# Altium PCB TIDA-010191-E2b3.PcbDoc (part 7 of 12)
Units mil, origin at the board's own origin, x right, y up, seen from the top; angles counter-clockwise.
Board outline 9842.52 x 9842.4 mil, 6 copper layers (Layer 1 - Top Layer, Layer 2 - GND Layer, Layer 3 - Signal, Layer 4 - Signal, Layer 5 - GND, Bottom Layer), stack 59.9 mil thick; 1178 components, 642 nets, 3329 pads, 2967 vias.
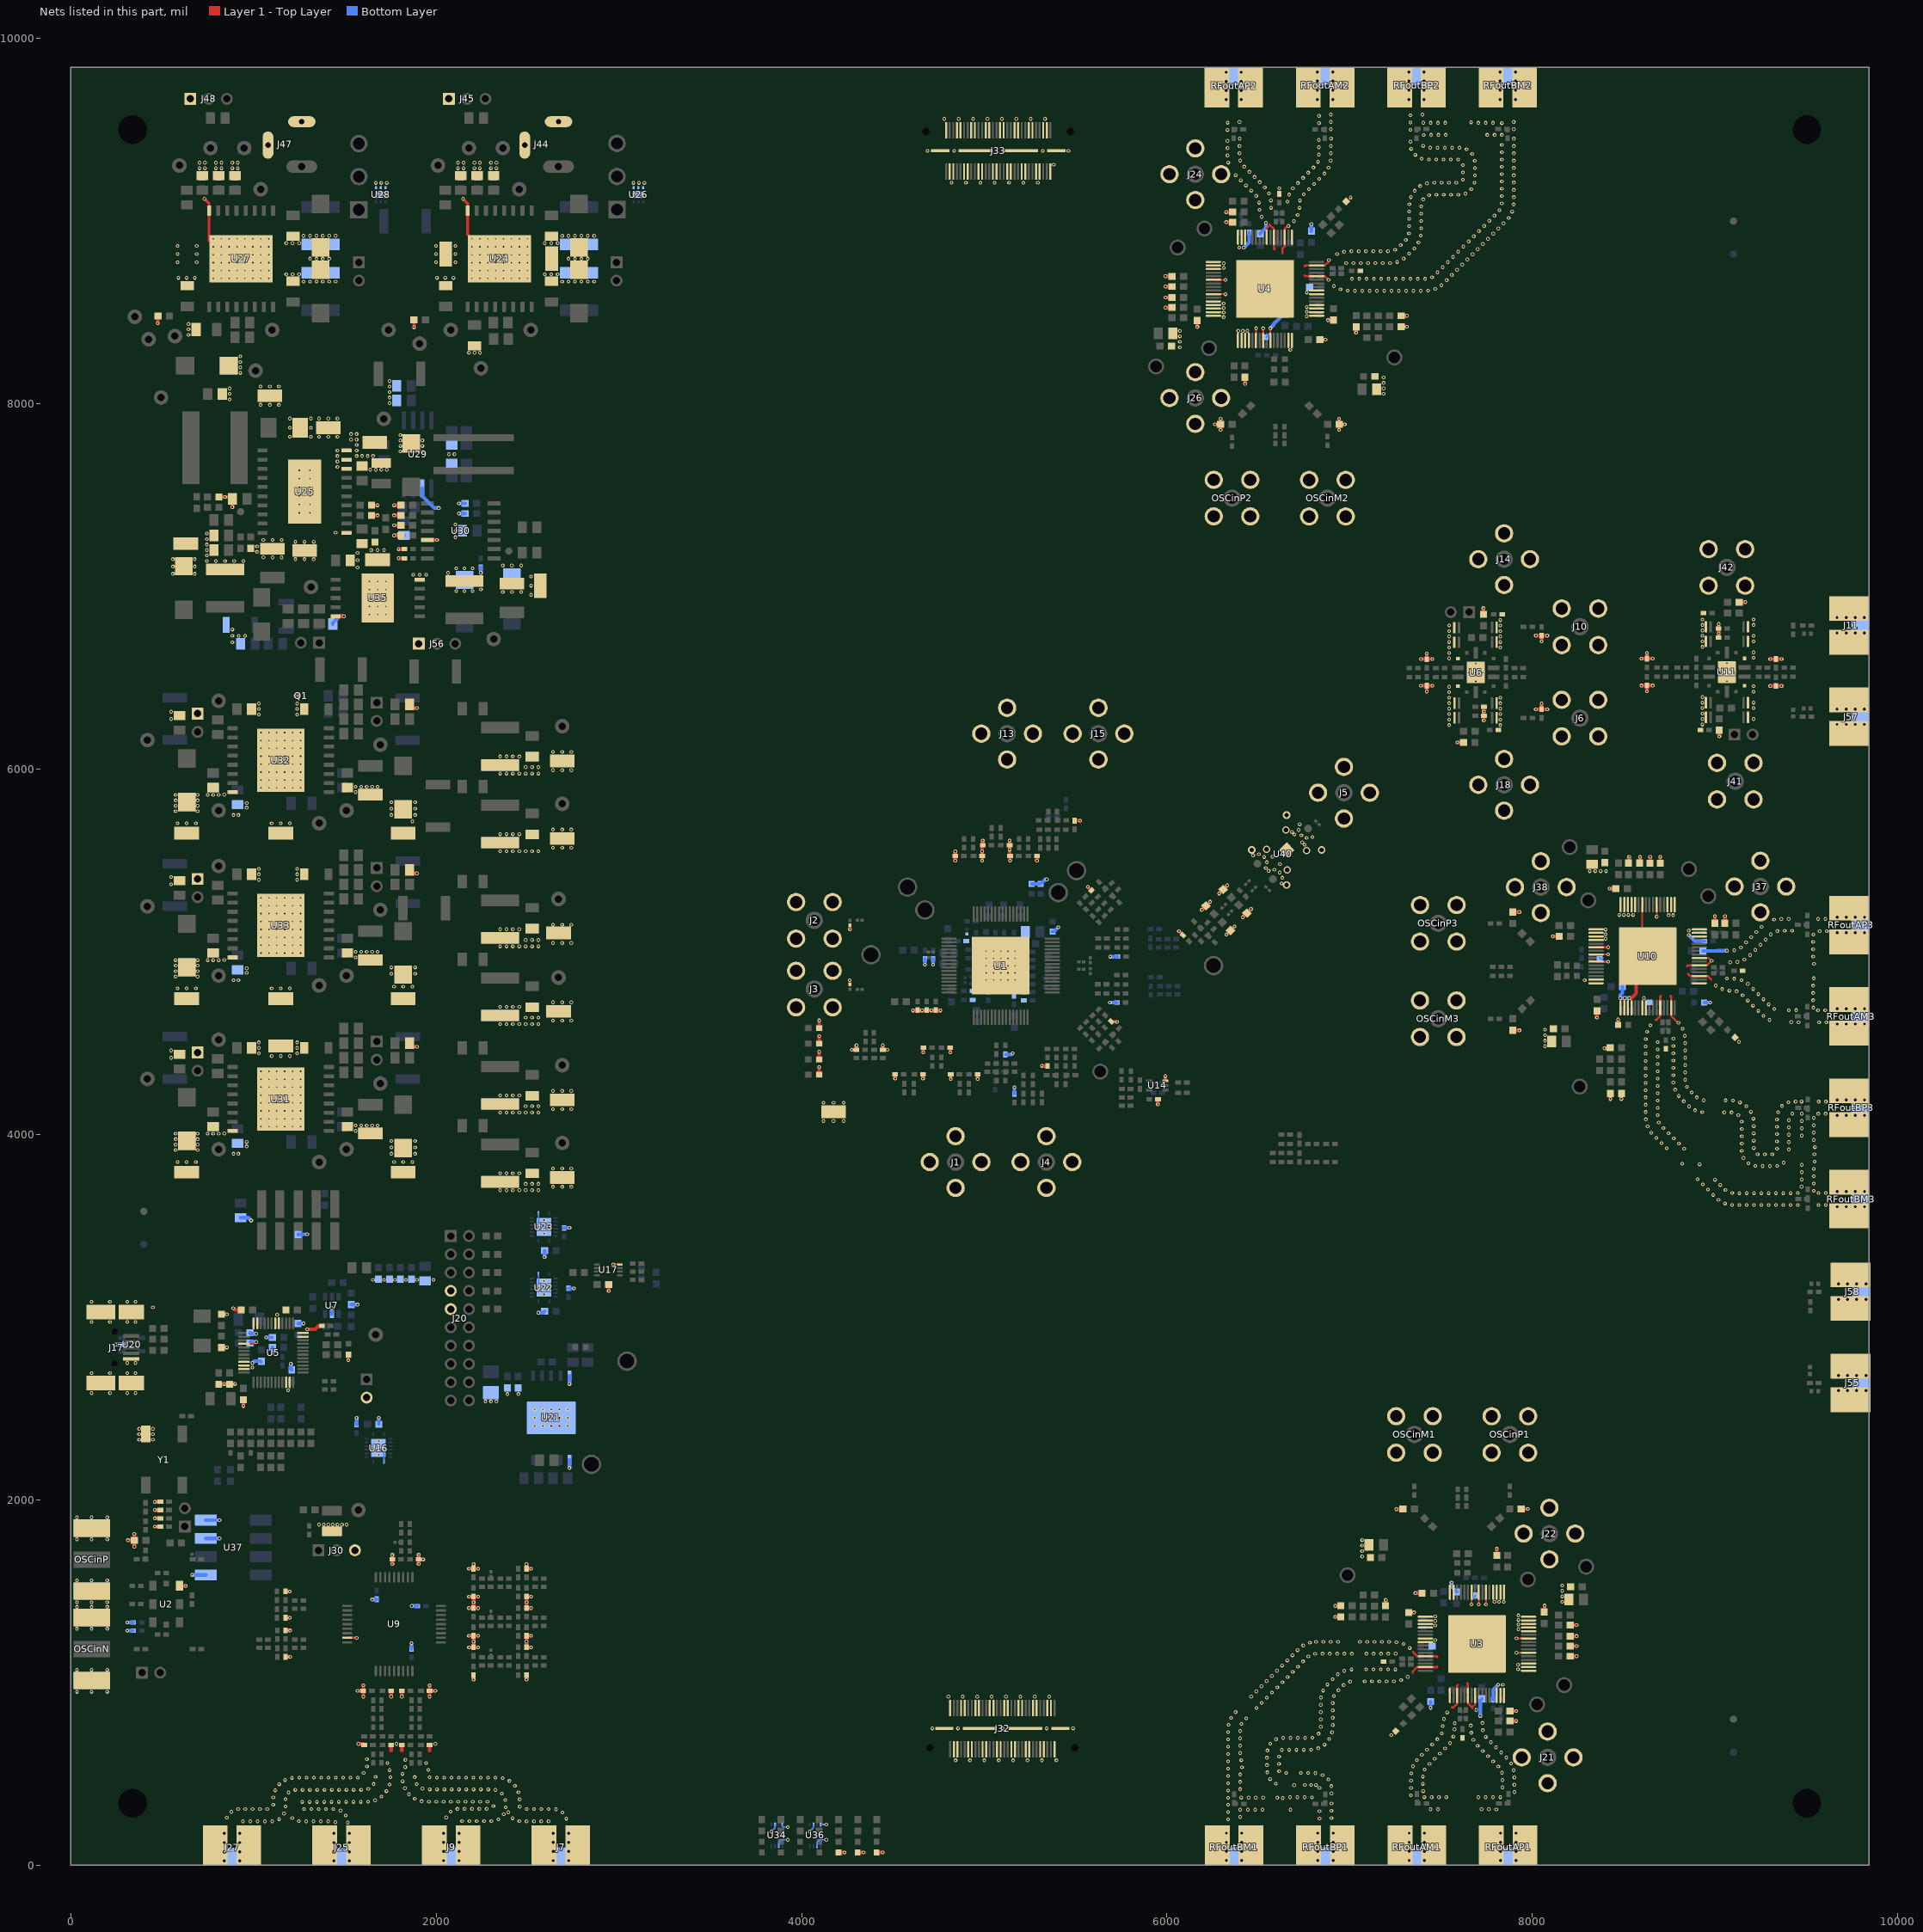
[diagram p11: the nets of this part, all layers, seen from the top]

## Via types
v1: diameter 20, hole 10, Layer 1 - Top Layer to Bottom Layer, tented both sides, 2595 vias
v2: diameter 19.68, hole 7.87, Layer 1 - Top Layer to Bottom Layer, 308 vias
v3: diameter 19.68, hole 7.87, Layer 1 - Top Layer to Bottom Layer, tented both sides, 25 vias
v4: diameter 20, hole 10, Layer 1 - Top Layer to Bottom Layer, 21 vias
v5: diameter 41, hole 25, Layer 1 - Top Layer to Bottom Layer, 10 vias
v6: diameter 24, hole 12, Layer 1 - Top Layer to Bottom Layer, tented both sides, 4 vias
v7: diameter 24, hole 8, Layer 1 - Top Layer to Bottom Layer, tented both sides, 1 vias
v8: diameter 24/24/24/24/24/24 (per signal layer), hole 8, Layer 1 - Top Layer to Bottom Layer, tented both sides, 1 vias
v9: diameter 30, hole 12, Layer 1 - Top Layer to Bottom Layer, tented both sides, 1 vias
v10: diameter 20/20/20/20/20/20 (per signal layer), hole 10, Layer 1 - Top Layer to Bottom Layer, tented both sides, 1 vias

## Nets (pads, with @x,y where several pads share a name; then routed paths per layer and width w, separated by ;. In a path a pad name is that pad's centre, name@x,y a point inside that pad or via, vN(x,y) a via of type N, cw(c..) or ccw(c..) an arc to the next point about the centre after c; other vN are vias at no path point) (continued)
GND: C1.2 C2.2 C7.2 C10.2 C11.2 C13.1 C14.2 C18.1 C19.1 C20.1 C21.1 C22.1 C23.2 C24.2 C25.2 C26.1 C27.2 C28.2 C29.2 C30.2 C31.1 C32.2 C33.2 C34.2 C35.2 C40.1 C41.2 C42.1 C43.2 C45.2 C46.1 C47.1 C49.1 C50.1 C51.1 C52.1 C53.1 C54.1 C55.1 C56.1 C58.1 C59.2 C61.2 C62.2 C63.2 C67.2 C68.2 C73.1 C74.2 C75.2 C76.1 C77.2 C78.2 C83.1 C84.1 C85.1 C93.2 C94.2 C95.2 C96.2 C97.2 C98.1 C99.2 C100.1 C101.2 C102.2 C103.2 C104.2 C106.2 C107.2 C108.2 C109.2 C110.2 C111.2 C112.2 C113.1 C114.2 C115.1 C117.2 C121.1 C122.1 C123.1 C124.1 C125.1 C126.2 C127.1 C128.1 C129.1 C130.1 C131.1 C138.1 C139.1 C140.1 C143.1 C144.2 C145.1 C147.2 C148.2 C149.2 C150.1 C151.2 C152.2 C154.1 C155.1 C156.1 C157.1 C159.2 C160.1 C161.1 C162.1 C163.1 C164.1 C165.1 C167.1 C168.2 C169.1 C170.1 C171.2 C173.1 C174.2 C175.2 C180.2 C182.2 C183.2 C184.2 C185.2 C186.1 C187.1 C188.1 C189.1 C190.2 C196.2 C197.2 C198.2 C199.2 C200.1 C201.2 C205.2 C206.2 C208.1 C209.2 C210.2 C211.1 C212.2 C213.2 C218.2 C219.2 C220.2 C221.2 C222.2 C226.1 C227.2 C228.1 C230.2 C231.2 C232.2 C233.2 C234.2 C235.2 C236.2 C237.2 C238.1 C239.2 C240.2 C241.2 C242.2 C243.2 C244.2 C245.2 C246.1 C247.1 C248.2 C252.2 C253.2 C254.1 C255.2 C256.1 C257.2 C258.2 C259.2 C260.2 C261.2 C262.1 C263.1 C265.2 C266.2 C267.1 C268.1 C269.2 C270.2 C272.2 C273.2 C274.2 C275.2 C276.2 C277.2 C278.2 C279.2 C280.1 C281.1 C282.2 C283.2 C284.2 C285.2 C286.1 C287.1 C288.2 C289.2 C291.2 C292.2 C293.2 C294.2 C295.2 C296.2 C297.2 C298.2 C299.1 C300.1 C301.2 C302.2 C303.2 C304.2 C305.1 C306.1 C307.2 C308.2 C310.2 C311.2 C312.2 C313.2 C314.2 C315.2 C326.2 C327.2 C328.2 C329.2 C334.2 C335.2 C337.2 C339.1 C340.1 C341.2 C342.2 C343.2 C344.2 C346.2 C348.2 C349.2 C350.2 C351.2 C352.2 C353.2 C354.2 C355.2 C356.2 D1.2 D2.2 D3.2 D4.2 D5.2 D6.2 D10.2 D12.2 D13.2 D18.2 D19.2 D20.2 D22.1 J1.2 J1.3 J1.4 J1.5 J2.2 J2.3 J2.4 J2.5 J3.2 J3.3 J3.4 J3.5 J4.2 J4.3 J4.4 J4.5 J5.2 J5.3 J5.4 J5.5 J6.2 J6.3 J6.4 J6.5 J7.2 J7.3 J7.4 J9.2 J9.3 J9.4 J10.2 J10.3 J10.4 J10.5 J11.2 J11.3 J11.4 J13.2 J13.3 J13.4 J13.5 J14.2 J14.3 J14.4 J14.5 J15.2 J15.3 J15.4 J15.5 J17.5 J17.6 J17.7 J17.8 J17.9 J18.2 J18.3 J18.4 J18.5 J20.7 J20.9 J21.2 J21.3 J21.4 J21.5 J22.2 J22.3 J22.4 J22.5 J24.2 J24.3 J24.4 J24.5 J25.2 J25.3 J25.4 J26.2 J26.3 J26.4 J26.5 J27.2 J27.3 J27.4 J30.3 J32.2 J32.3 J32.5 J32.8 J32.10 J32.11 J32.13 J32.16 J32.18 J32.19 J32.21 J32.24 J32.26 J32.27 J32.29 J32.32 J32.34 J32.35 J32.37 J32.40 J32.42 J32.43 J32.45 J32.48 J32.50 J32.51 J32.53 J32.56 J32.58 J32.59 J32.MP1 J32.MP2 J32.MP3 J32.MP4 J33.2 J33.3 J33.5 J33.8 J33.10 J33.11 J33.13 J33.16 J33.18 J33.19 J33.21 J33.24 J33.26 J33.27 J33.29 J33.32 J33.34 J33.35 J33.37 J33.40 J33.42 J33.43 J33.45 J33.48 J33.50 J33.51 J33.53 J33.56 J33.58 J33.59 J33.MP1 J33.MP2 J33.MP3 J33.MP4 J37.2 J37.3 J37.4 J37.5 J38.2 J38.3 J38.4 J38.5 J39.2 J41.2 J41.3 J41.4 J41.5 J42.2 J42.3 J42.4 J42.5 J44.2 J44.3 J45.1 J47.2 J47.3 J48.1 J50.1 J52.1 J54.1 J55.2 J55.3 J55.4 J56.1 J57.2 J57.3 J57.4 J58.2 J58.3 J58.4 NT2.2 OSCinM1.2 OSCinM1.3 OSCinM1.4 OSCinM1.5 OSCinM2.2 OSCinM2.3 OSCinM2.4 OSCinM2.5 OSCinM3.2 OSCinM3.3 OSCinM3.4 OSCinM3.5 OSCinN.2 OSCinN.3 OSCinN.4 OSCinN.5 OSCinP1.2 OSCinP1.3 OSCinP1.4 OSCinP1.5 OSCinP2.2 OSCinP2.3 OSCinP2.4 OSCinP2.5 OSCinP3.2 OSCinP3.3 OSCinP3.4 OSCinP3.5 OSCinP.2 OSCinP.3 OSCinP.4 OSCinP.5 Q1.3 R15.1 R16.1 R17.1 R18.1 R23.1 R24.1 R28.1 R34.2 R35.1 R40.2 R52.1 R53.2 R60.2 R61.2 R64.2 R65.2 R66.1 R67.1 R96.2 R99.1 R100.2 R104.2 R108.1 R110.1 R113.1 R118.2 R119.2 R123.1 R129.1 R133.1 R134.1 R139.1 R140.1 R153.2 R171.1 R174.1 R213.2 R214.2 R264.2 R267.2 R268.2 R270.2 R277.2 R285.1 R291.1 R297.1 R298.1 R299.2 R304.1 R318.1 R322.2 R329.1 R330.1 R334.2 R335.2 R337.1 R339.2 R342.2 R345.1 R348.2 R351.1 R366.2 R371.1 R375.1 R376.1 R379.1 R380.1 R389.1 R390.1 R401.1 R402.1 R403.1 R404.1 R412.2 R414.2 R415.1 R416.1 R417.1 R418.1 R419.1 R421.1 R426.1 R427.1 R434.1 R435.1 R436.1 R437.1 R444.1 R445.1 R446.1 R447.1 R454.1 R455.1 R456.1 R457.1 R464.1 R465.1 R466.1 R467.1 R474.1 R475.1 R476.1 R477.1 R479.1 R480.1 R490.1 R491.1 R492.1 R493.1 R494.1 R495.1 R496.1 R497.1 R498.1 R499.1 R500.1 R501.1 R510.1 R512.1 R513.1 R521.1 R523.1 R524.1 R534.1 R536.1 R537.1 R551.1 R552.1 RFoutAM1.2 RFoutAM1.3 RFoutAM1.4 RFoutAM2.2 RFoutAM2.3 RFoutAM2.4 RFoutAM3.2 RFoutAM3.3 RFoutAM3.4 RFoutAP1.2 RFoutAP1.3 RFoutAP1.4 RFoutAP2.2 RFoutAP2.3 RFoutAP2.4 RFoutAP3.2 RFoutAP3.3 RFoutAP3.4 RFoutBM1.2 RFoutBM1.3 RFoutBM1.4 RFoutBM2.2 RFoutBM2.3 RFoutBM2.4 RFoutBM3.2 RFoutBM3.3 RFoutBM3.4 RFoutBP1.2 RFoutBP1.3 RFoutBP1.4 RFoutBP2.2 RFoutBP2.3 RFoutBP2.4 RFoutBP3.2 RFoutBP3.3 RFoutBP3.4 TP5.1 TP22.1 TP23.1 TP24.1 TP25.1 TP26.1 TP36.1 TP43.1 TP48.1 TP49.1 TP50.1 TP51.1 TP56.1 TP61.1 TP62.1 TP63.1 TP64.1 TP69.1 TP74.1 TP75.1 TP76.1 TP77.1 TP80.1 TP81.1 TP82.1 U1.65 U2.3@596.03,1530.27 U3.1 U3.2 U3.3 U3.4 U3.6 U3.8 U3.10 U3.15 U3.16 U3.17 U3.18 U3.19 U3.20 U3.23 U3.24 U3.28 U3.31 U3.33 U3.35 U3.38 U3.40 U3.46 U3.47 U3.48 U3.49 U3.50 U3.51 U3.54 U3.58 U3.60 U3.61 U3.62 U3.63 U3.64 U3.65 U4.1 U4.2 U4.3 U4.4 U4.6 U4.8 U4.10 U4.15 U4.16 U4.17 U4.18 U4.19 U4.20 U4.23 U4.24 U4.28 U4.31 U4.33 U4.35 U4.38 U4.40 U4.46 U4.47 U4.48 U4.49 U4.50 U4.51 U4.54 U4.58 U4.60 U4.61 U4.62 U4.63 U4.64 U4.65 U5.4 U5.9 U5.10 U5.11 U5.22 U5.23 U5.35 U5.36 U5.41 U5.42 U5.47 U5.48 U6.11 U6.14 U6.15 U7.2 U9.8 U10.1 U10.2 U10.3 U10.4 U10.6 U10.8 U10.10 U10.15 U10.16 U10.17 U10.18 U10.19 U10.20 U10.23 U10.24 U10.28 U10.31 U10.33 U10.35 U10.38 U10.40 U10.46 U10.47 U10.48 U10.49 U10.50 U10.51 U10.54 U10.58 U10.60 U10.61 U10.62 U10.63 U10.64 U10.65 U11.11 U11.14 U11.15 U14.3 U16.8 U16.17 U17.4 U20.2 U21.5 U21.6 U21.11@2630,2450 U22.8 U22.17 U23.8 U23.17 U24.8 U24.17 U25.1 U25.8 U25.9 U25.10 U25.21 U26.1 U26.2 U26.3 U26.7@3107.56,9145 U27.8 U27.17 U28.1 U28.2 U28.3 U28.7@1697.56,9145 U29.2 U30.12 U31.8 U31.17 U32.8 U32.17 U33.8 U33.17 U34.2 U34.4 U34.6 U35.5 U35.10 U35.11@1680,6937.56 U36.2 U36.4 U36.6 U37.1 U37.3 U37.4 U40.4 Y1.2 | length 14671.6
  Layer 1 - Top Layer w8: U5.4@948.58,2854.8 1001.56,2854.8 1011.75,2865 v1(1015,2865) ; v3(5090,4925) v3(5129.37,4925) 5160,4925 U1.65@5189.53,4895.47
  Layer 1 - Top Layer w10: v1(2970,3289.53) U17.4@3005.92,3289.53 ; U4.58@6253.61,8600.5 v1(6320,8600.5) ; U4.54@6253.61,8679.24 v1(6320,8679.24) ; U4.6@6486.88,8347.55 v1(6486.88,8413.94) ; U4.8@6526.25,8347.55 v1(6526.25,8413.94) ; U4.40@6545.93,8912.51 6546.28,8912.86 6546.28,8961.28 6557.5,8972.5 ; U4.10@6565.62,8347.55 v1(6565.62,8413.94) ; v1(7666.73,1429.04) U3.10@7666.73,1495.43 ; 7674.85,870.48 7686.07,881.7 U3.40@7686.07,930.13 ; v1(7706.1,1429.04) U3.8@7706.1,1495.43 ; v1(7745.47,1429.04) U3.6@7745.47,1495.43 ; v1(7912.35,1163.74) U3.54@7978.74,1163.74 ; v1(7912.35,1242.48) U3.58@7978.74,1242.48 ; U10.10@8348.05,4946.93 v1(8414.44,4946.93) ; U10.8@8348.05,4986.3 v1(8414.44,4986.3) ; U10.6@8348.05,5025.67 v1(8414.44,5025.67) ; U10.58@8601,5258.94 8601,5005.98 U10.65@8630.53,4976.46 ; v1(8679.74,5192.55) U10.54@8679.74,5258.94 ; U10.40@8913.01,4966.61 8965.39,4966.61 v1(8980.64,4951.36)
  Layer 1 - Top Layer w12: U9.8@1513.58,1245.48 v1(1565.15,1245.48) ; 6561.19,8980.15 6585.3,8956.03 U4.38@6585.3,8912.51 6585.3,8850.35 6589.36,8846.29 ; 6633,8827 6633,8852 6644.36,8863.36 U4.35@6644.36,8912.51 6644.36,8958.32 v1@6664.02,8977.98 ; 6752.35,8702.98 6756.41,8698.93 U4.28@6818.57,8698.93 6864.38,8698.93 v1(6884.04,8679.27) ; 6752.35,8753.93 6756.41,8757.98 U4.31@6818.57,8757.98 6863.89,8757.98 6884.69,8778.78 6884.69,8785.27 v1(6886.22,8786.8) ; 7345,1055 7345,1062.03 7367.97,1085 U3.31@7413.78,1085 7475.94,1085 7480,1089.06 ; 7346.6,1168.18 7358.46,1156.33 7358.46,1155.91 7370.31,1144.06 U3.28@7413.78,1144.06 7475.94,1144.06 7480,1140 ; 7560,865 7568.33,865 7587.99,884.66 U3.35@7587.99,930.47 7587.99,982.99 7592.05,987.05 ; 7642.99,996.69 7647.05,992.64 U3.38@7647.05,930.47 7647.05,886.95 7671.16,862.84 ; 8675.34,4628.5 8679.76,4628.5 ; 8683.49,4634.55 8699.43,4650.49 8699.43,4756.14 8703.48,4760.2 ; 8754.43,4760.2 8758.48,4756.14 8758.48,4650.46 8782.6,4626.34 8782.74,4626.34 8797.13,4611.96 v1(8799.29,4611.96) ; 8846.79,4923.19 8850.84,4927.24 U10.38@8913.01,4927.24 8956.53,4927.24 v1(8980.64,4951.36) ; 8851,4880 8862.81,4868.19 U10.35@8913.01,4868.19 8958.82,4868.19 8978.48,4848.53
  Layer 1 - Top Layer w15: v1(732.5,9122.5) 757.56,9097.44 U27.8@757.56,9058.5 757.56,8892.56 ; v1(2147.5,9122.5) 2172.56,9097.44 U24.8@2172.56,9058.5 2172.56,8926.69 v2(2195.98,8903.27) ; R100.2@4263.74,4822.72 v1(4263.74,4845) ; v1(4265,5124.72) R99.1@4265,5147.01
  Layer 1 - Top Layer w20: v1(313.5,1780) R171.1@348.5,1780 ; v1(348.5,1745) R171.1@348.5,1780 ; v1(348.5,1815) R171.1@348.5,1780 ; v1(461.26,1855) C19.1@491.38,1855 ; v1(461.26,1900) C22.1@491.38,1900 ; v1(461.26,1945) C83.1@491.38,1945 ; v1(461.26,1990) C84.1@491.38,1990 ; v1(476.92,8441.05) 476.92,8480.42 R480.1@477.5,8481 ; U2.3@596.03,1530.27 v1(630,1530.27) ; C112.2@810,2633.5 811.5,2635 v1(840,2635) C114.2@870.45,2635 ; R415.1@811.5,7490 v1(845,7490) C239.2@885,7490 ; C125.1@824.55,3016.63 C125.1@825,3017.09 825.45,3017.54 v1(854.55,3017.54) ; C126.2@825,2834.09 825.91,2835 v1(855,2835) ; C114.2@870,2634.09 870.91,2635 v1(900,2635) ; v1(885,7435) C239.2@885,7480 ; v1(890,3050) 900,3040 C110.2@933.5,3040 ; v1(945,2515) C108.2@945,2548.5 ; C115.1@1173.5,3035 C115.1@1178.5,3040 ; R34.2@1175,1355.38 v1(1200,1355.38) ; R40.2@1175,1499.62 v1(1200,1499.62) ; R299.2@1176,1141.38 v1(1201,1141.38) ; R270.2@1176,1285.62 v1(1201,1285.62) ; v1(1227.75,6401.42) Q1.3@1242.75,6401.42 ; v1(1295,2935) 1337.63,2935 1356.13,2953.5 R174.1@1374.88,2953.5 ; U35.10@1450.08,6837.56 v1(1495,6837.56) ; v1(1520,2765) D10.2@1520,2796.06 ; v1(1570.09,955) R402.1@1601.38,955 ; v1(1575,665) 1601.38,665 R404.1@1606.38,660 ; v1(1601.38,923.72) R402.1@1601.38,955 ; v1(1601.38,986.28) R402.1@1601.38,955 ; R414.2@1646.5,7390 v1(1680,7390) ; R412.2@1646.5,7445 v1(1680,7445) ; 1753.62,628.72 R403.1@1753.62,660 ; v1(1753.62,923.72) R401.1@1753.62,955 ; v1(1760.38,1650) R444.1@1760.38,1675 v1(1760.38,1700) ; v1(1770,7280) R499.1@1808.5,7280 ; v1(1770,7335) R501.1@1808.5,7335 ; v1(1770,7390) R496.1@1808.5,7390 ; v1(1770,7445) R498.1@1808.5,7445 ; v1(1795,7155) R497.1@1826.38,7155 ; v1(1795,7205) R500.1@1826.38,7205 ; 1812.38,628.72 R437.1@1812.38,660 ; v1(1812.38,923.72) R435.1@1812.38,955 ; R513.1@1855,4500 1855,4495.47 1870,4480.47 v1(1895,4480.47) ; R537.1@1855,5450 1855,5445.47 1870,5430.47 v1(1895,5430.47) ; R524.1@1855,6354.53 1855,6350 1870,6335 v1(1895,6335) ; R419.1@1878.5,8460 1879.5,8459 v1(1879.5,8419.24) ; v1(1904.62,1650) R445.1@1904.62,1675 ; v1(1904.62,1700) R445.1@1904.62,1675 ; v1(1929.62,1675) R445.1@1904.62,1675 ; U30.12@1951.93,7255 v1(2005,7255) ; 1964.62,628.72 R436.1@1964.62,660 ; v1(1964.62,923.72) R434.1@1964.62,955 ; v1(1964.62,986.28) R434.1@1964.62,955 ; v1(1995.91,955) R434.1@1964.62,955 ; v1(2180,1193.62) R475.1@2205,1193.62 ; v1(2180,1256.38) R465.1@2205,1256.38 ; v1(2180,1408.62) R464.1@2205,1408.62 ; v1(2180,1471.38) R455.1@2205,1471.38 ; v1(2180,1623.62) R454.1@2205,1623.62 ; v1(2205,1016.38) R474.1@2205,1041.38 ; v1(2205,1648.62) R454.1@2205,1623.62 ; v1(2230,1193.62) R475.1@2205,1193.62 ; v1(2230,1256.38) R465.1@2205,1256.38 ; v1(2230,1408.62) R464.1@2205,1408.62 ; v1(2230,1471.38) R455.1@2205,1471.38 ; v1(2230,1623.62) R454.1@2205,1623.62 ; v1(2495,1016.38) R476.1@2495,1041.38 ; v1(2495,1648.62) R456.1@2495,1623.62 v1(2520,1623.62) ; v1(2520,1193.62) R477.1@2495,1193.62 v1(2495,1225) R467.1@2495,1256.38 v1(2520,1256.38) ; v1(2520,1408.62) R466.1@2495,1408.62 v1(2495,1440) R457.1@2495,1471.38 v1(2520,1471.38) ; v1(2944.79,3144.63) C199.2@2944.79,3179.63 ; D2.2@4096.42,4328.46 v1(4096.42,4370) ; D1.2@4096.42,4412 v1(4096.42,4453.53) ; D4.2@4096.42,4498.46 v1(4096.42,4540) ; D3.2@4096.42,4583.46 v1(4096.42,4625) ; D18.2@4201.28,70.59 v1(4235,70.59) ; v1(4275.38,4463.76) R446.1@4300.38,4463.76 v1(4300.38,4488.76) ; D19.2@4306.28,70.59 v1(4340,70.59) ; D20.2@4411.28,70.59 v1(4445,70.59) ; v1(4444.62,4488.76) R447.1@4444.62,4463.76 v10(4469.62,4463.76) ; v1(4512.1,4306.16) R24.1@4512.1,4331.16 ; v1(4610,4680) v1(4660,4680) v1(4710,4680) v1(4760,4680) ; v1(4664.35,4306.16) R23.1@4664.35,4331.16 ; v1(4666.38,4450) R18.1@4666.38,4475 ; v1(4813.62,4450) R17.1@4813.62,4475 ; v1(4816.38,4305) R16.1@4816.38,4330 ; v1(4841.38,5500) R60.2@4841.38,5525 v1(4841.38,5550) ; v1(4963.62,4305) R15.1@4963.62,4330 ; v1(4988.62,5500) R61.2@4988.62,5525 v1(4988.62,5550) 4988.62,5583.19 4990.43,5585 R66.1@4991.38,5585 v1(4991.38,5610) ; v1(5138.62,5610) R67.1@5138.62,5585 v1(5138.62,5560) 5138.62,5526.81 5140.43,5525 R64.2@5141.38,5525 v1(5141.38,5500) ; v1(5288.62,5500) R65.2@5288.62,5525 ; v1(5315,4376.38) R339.2@5345,4376.38 ; R366.2@5495,5718.62 v1(5525,5718.62) ; v1(5566.7,5356.7) R291.1@5586.7,5336.7 ; R285.1@5694.7,4620.3 5697.45,4617.55 v1(5726.44,4617.55) ; v1(5950,4165) 5950,4193.58 C2.2@5950.51,4194.09 ; U14.3@5991.18,4300 v1(5991.18,4320) ; v1(5992.12,8527.44) C128.1@6027.12,8527.44 ; v1(5992.12,8582.44) C144.2@6027.12,8582.44 ; v1(5992.12,8642.44) C150.1@6027.12,8642.44 ; v1(5992.12,8698.82) C190.2@6027.12,8698.82 ; v1(6065.29,5114.2) 6087.56,5091.93 C40.1@6087.56,5091.7 C40.1@6087.56,5091.47 ; v1(6165.61,8420.94) C145.1@6165.61,8455.94 ; v1(6190,5230) 6212.27,5252.27 R119.2@6212.73,5252.27 v1(6235,5274.54) ; v1(6262.46,7888.07) R348.2@6293.41,7888.07 ; v1(6285.23,5320) R118.2@6307.5,5342.27 ; v1(6293.41,7857.12) R348.2@6293.41,7888.07 ; v1(6293.41,7919.01) R348.2@6293.41,7888.07 ; R118.2@6307.96,5342.27 v1(6330.23,5364.54) ; v1(6323.5,8995) C147.2@6358.5,8995 ; v1(6323.5,9050) C139.1@6358.5,9050 ; v1(6324.77,5095.46) 6347.04,5117.73 R110.1@6347.27,5117.73 6347.5,5117.73 v1(6369.77,5140) ; v1(6414.77,5190.46) 6437.04,5212.73 R108.1@6437.27,5212.73 6437.5,5212.73 v1(6459.77,5235) ; v1(6427.07,8110.21) C151.2@6427.07,8145.21 ; C143.1@6836.4,8352.44 v1(6867.35,8352.44) ; v1(6880,8458.5) C130.1@6910,8458.5 ; v1(6920,1360.54) R96.2@6950.95,1360.54 ; v1(6920,1420.54) C59.2@6950.95,1420.54 ; v1(6941.86,7857.12) R351.1@6941.86,7888.07 ; v1(6941.86,7919.01) R351.1@6941.86,7888.07 ; v1(6972.81,7888.07) R351.1@6941.86,7888.07 ; v1(7034.91,8390) C148.2@7034.91,8420.94 ; C62.2@7197.45,1422.04 v1(7197.45,1452.98) ; v1(7255,1950) 7289.25,1950 R113.1@7290.86,1951.61 ; C149.2@7281.4,8422.44 v1(7312.35,8422.44) ; R322.2@7281.4,8482.44 v1(7312.35,8482.44) ; C55.1@7322.35,1384.48 v1(7352.35,1384.48) ; v1(7359.67,1490.83) C98.1@7394.67,1490.83 ; v1(7390.09,6457.17) C67.2@7421.38,6457.17 ; v1(7390.09,6602.83) C68.2@7421.38,6602.83 ; v1(7421.38,6425.88) C67.2@7421.38,6457.17 ; v1(7421.38,6634.12) C68.2@7421.38,6602.83 ; v1(7452.66,6457.17) C67.2@7421.38,6457.17 ; v1(7452.66,6602.83) C68.2@7421.38,6602.83 ; v1(7588.94,6146.75) R140.1@7622.44,6146.75 ; C78.2@7731.49,6848.15 v1(7731.49,6881.75) ; v1(7733.94,6266.75) v1(7733.94,6316.75) 7733.94,6340.47 C77.2@7735.12,6341.65 ; C102.2@7805.28,1697.77 v1(7805.28,1732.77) ; C47.1@7876.5,790 v1(7911.5,790) ; C101.2@7876.5,845 v1(7911.5,845) ; R318.1@7893.15,4570.77 v1(7928.15,4570.77) ; R277.2@7893.15,5218.76 v1(7928.15,5218.76) ; R104.2@7940.13,1951.33 v1(7975.13,1951.33) ; v1(8018.72,6328.62) R123.1@8050,6328.62 ; v1(8018.72,6731.38) R129.1@8050,6731.38 ; v1(8050,6359.91) R123.1@8050,6328.62 ; v1(8050,6700.09) R129.1@8050,6731.38 ; C100.1@8066.74,1387.04 v1(8066.74,1422.04) ; v1(8081.28,6328.62) R123.1@8050,6328.62 ; v1(8081.28,6731.38) R129.1@8050,6731.38 ; v1(8110.71,5085.48) C180.2@8145.71,5085.48 ; C104.2@8206.5,1145 v1(8241.5,1145) ; C58.1@8206.5,1200 v1(8241.5,1200) ; C99.2@8206.5,1255 v1(8241.5,1255) ; C46.1@8206.5,1315 v1(8241.5,1315) ; v1(8352.65,4640.85) C167.1@8352.65,4675.85 ; v1(8394.16,4472.55) C175.2@8425.1,4472.55 ; v1(8421.44,5346.94) C169.1@8456.44,5346.94 ; v1(8426.6,4195.11) C171.2@8426.6,4226.06 ; C157.1@8468.44,4600 v1(8468.44,4630) ; v1(8486.6,4195.11) R264.2@8486.6,4226.06 ; C165.1@8529.32,5485.43 v1(8529.32,5520.43) ; v1(8530.5,4747.55) 8541.95,4747.55 8567.7,4773.3 8567.7,4913.63 U10.65@8630.53,4976.46 ; C168.2@8589.32,5485.43 v1(8589.32,5520.43) ; v1(8595.74,6458.13) R330.1@8627.02,6458.13 ; v1(8595.74,6605.37) R329.1@8627.02,6605.37 ; v1(8627.02,6426.84) R330.1@8627.02,6458.13 ; v1(8627.02,6636.65) R329.1@8627.02,6605.37 ; C170.1@8644.32,5485.43 v1(8644.32,5520.43) ; v1(8658.3,6458.13) R330.1@8627.02,6458.13 ; v1(8658.3,6605.37) R329.1@8627.02,6605.37 ; C183.2@8699.32,5485.43 v1(8699.32,5520.43) ; C174.2@8998.48,5161.69 v1(8998.48,5196.69) ; C212.2@9018.82,6720.09 9020,6721.28 v1(9020,6745) v1(9020,6795) ; v1(9022.44,6180) C213.2@9022.44,6213.6 ; C164.1@9053.48,5161.69 v1(9053.48,5196.69) ; R379.1@9131.5,6915 v1(9165,6915) ; v1(9301.16,6456.47) C206.2@9332.44,6456.47 v1(9363.72,6456.47) ; v1(9301.16,6603.72) C205.2@9332.44,6603.72 v1(9363.72,6603.72) ; R475.1@2205,1193.62 v1(2205,1225) R465.1@2205,1256.38 ; R464.1@2205,1408.62 v1(2205,1440) R455.1@2205,1471.38
  Bottom Layer w8: U16.17@1685,2285 1714.53,2255.47 U16.8@1714.53,2210.2 ; U22.8@2560.47,3237.36 2560.47,3192.09 U22.17@2590,3162.56 ; U23.8@2560.47,3569.8 2560.47,3524.53 U23.17@2590,3495 ; v1(3835,185) 3855.16,205.16 U34.2@3855.16,224.06 ; U34.6@3874.84,105.94 3874.84,126.63 3888.21,140 v1(3925,140) ; U34.4@3894.53,224.06 3894.53,215.47 3900,210 v1(3925,210) ; v1(4045,185) 4065.16,205.16 U36.2@4065.16,224.06 ; U36.6@4084.84,105.94 4084.84,126.63 4098.21,140 v1(4135,140) ; U36.4@4104.53,224.06 v1(4135,224.06)
  Bottom Layer w10: R342.2@6544.91,8364.69 6544.91,8368.62 6565.22,8388.94 6565.22,8413.54 v1(6565.62,8413.94) ; v1(7666.73,1429.04) 7667.13,1429.44 7667.13,1454.04 7687.45,1474.36 R214.2@7687.45,1478.3 ; R267.2@8365.18,4967.64 8369.12,4967.64 8389.44,4947.33 8414.04,4947.33 v1(8414.44,4946.93)
  Bottom Layer w20: v1(245,2851) U20.2@280.87,2851 ; v1(310,1285) C187.1@341.38,1285 ; v1(310,1330) C188.1@341.38,1330 ; v1(665,1590) U37.1@740,1590 ; U37.3@740,1790 v1(815,1790) ; U37.4@740,1890 v1(815,1890) ; NT2.2@930,3545 972.5,3545 v7(987.5,3530) ; C111.2@981.5,2860 986.5,2865 v1(1015,2865) ; C107.2@981.5,2915 986.5,2910 v1(1015,2910) ; v1(995,2750) 1005,2760 1036.69,2760 1041.5,2755.2 R153.2@1041.5,2758.5 ; v1(1070,2890) C117.2@1103.5,2890 ; C106.2@1103.5,2835 1105,2833.5 v1(1105,2805) ; v1(1205,2745) 1205,2717.09 C109.2@1210,2712.09 ; C113.1@1245,2966.5 v1(1275,2966.5) ; R304.1@1245,3454.06 1245.94,3455 v1(1295,3455) ; U7.2@1430,3018.35 v1(1430,3050) ; R552.1@1435,6795 1435,6801.5 1471.06,6837.56 v1(1495,6837.56) ; C124.1@1535,3069.59 v1(1570,3069.59) ; R371.1@1565,2413.62 v1(1565,2450) ; v1(1650,1455) 1673.62,1455 C95.2@1675,1456.38 ; C196.2@1686.5,2415 v1(1686.5,2450) ; v1(1770,7280) C261.2@1825,7280 ; C97.2@1865.15,1184.59 v1(1865.15,1215.96) ; v1(1866.38,1420) C96.2@1897.76,1420 ; U29.2@1924.09,7538.54 1924.09,7495.91 1990,7430 v1(2015,7430) ; v1(2125,7400) R495.1@2158.5,7400 ; v1(2125,7455) R493.1@2158.5,7455 ; v1(2245,7075) R494.1@2245,7106.38 ; v1(2560,3025) 2585.94,3025 C221.2@2593.5,3032.56 ; v1(2593.5,3330) C222.2@2593.5,3365 ; R390.1@2700,3488.62 2701.38,3490 v1(2730,3490) ; R389.1@2725,3158.62 v1(2755,3158.62) ; v1(2730,2175.16) U21.6@2730,2220.08 ; v1(2730,2635) U21.5@2730,2679.92 ; v1(4675,4930) C356.2@4675,4961.38 ; v1(4720,4930) C11.2@4720,4961.38 ; R345.1@5118.94,4438.62 5148.62,4438.62 v1(5155,4445) ; R337.1@5165,4223.62 v1(5165,4260) ; C20.1@5259.68,5372.56 C18.1@5307.5,5372.56 5308.48,5372.56 5333.43,5397.5 v1(5342.23,5397.5) ; C21.1@5373.57,5111.77 5381.77,5111.77 v1(5405,5135) ; v1(5688,4723.09) R297.1@5726.27,4723.09 ; v1(5690,4974.09) R298.1@5728.27,4974.09 ; v1(6420,8855) 6450,8885 R334.2@6450,8938.62 ; C152.2@6510,8931.5 6510,8932.48 6541.09,8963.58 v1(6541.09,8991.08) ; v1(6565.62,8413.94) 6582.22,8430.54 6582.22,8435.4 6616.51,8469.69 6628.63,8481.81 6636.3,8481.81 6645,8490.51 C129.1@6645,8491.5 ; C140.1@6790,8946.5 v1(6790,8985) ; v1(7442.35,862.98) C50.1@7442.35,896.49 ; v1(7557.35,1547.98) 7557.35,1525.13 7585,1497.48 C56.1@7585,1496.5 ; v1@7714.7,818.18 v1(7714.85,818.33) 7715,818.48 7715,904.14 C103.2@7722.35,911.49 ; R213.2@7784.74,907.42 7784.74,960.37 v1(7812.35,987.98) ; C155.1@8492.5,4810 8492.5,4775.35 8480.5,4763.35 v1(8480.5,4747.55) v1(8530.5,4747.55) ; v1(8855.5,5092.55) 8888.11,5059.94 R268.2@8941.06,5059.94 ; C182.2@8932.5,5005 9013.71,5005 9012.21,5006.5 v1(9063.79,5006.5) ; C154.1@8939.12,4722.55 v1(8972.62,4722.55)
  other v1: 1516.62,234.36 1448.36,236.32 943.02,241.35 983.02,241.35 1023.02,241.35 1063.02,241.35 1103.02,241.32 1288.68,241.35 1328.68,241.35 1368.68,241.35 1408.68,241.35 2495.52,241.35 2535.52,241.35 2575.52,241.35 2615.52,241.35 1248.7,242.54 2142.5,242.35 2182.5,242.35 2222.5,242.35 2262.5,242.35 2302.5,242.35 2455.53,242.3 6334.54,251.49 2341.39,251.7 1141.13,253.48 2713.21,255.77 6834.54,256.56 2418.8,258.14 1212.35,259.25 6899.79,259.01 854.91,260.9 2055.06,262.25 6399.79,264.96 1505.4,272.76 2370.07,279.59 1167.71,283.37 2691.47,289.35 2395.32,290.52 6334.54,291.49 879.03,292.81 2079.34,294.04 6834.54,296.56 6899.79,299.01 1476.18,300.07 6442.34,304.61 6482.34,304.61 6522.34,304.61 6675.68,304.61 6399.79,304.96 7801.9,306.47 2655.66,307.15 7442.31,307.07 7482.31,307.07 7721.91,307.07 7761.91,307.07 916.07,307.91 956.06,308.65 996.06,308.65 1036.06,308.65 1076.06,308.65 1277.11,308.65 1317.11,308.65 1357.11,308.65 1397.11,308.65 1437.11,308.65 2116.45,308.96 2495.68,308.65 2535.68,308.65 2575.68,308.65 2615.68,308.65 2156.45,309.65 2196.45,309.65 2236.45,309.65 2276.45,309.65 2380.87,318.11 2457.65,321.02 1175.65,322.57 2313.35,325.07 6333.94,331.49 1108.35,332.26 6900.39,339.01 1267.55,347.49 1307.55,347.49 1347.55,347.49 1387.55,347.49 1427.55,347.49 1467.55,347.49 1507.55,347.49 1547.55,347.49 1587.55,347.49 1627.55,348.04 1960.93,348.49 2000.93,348.49 2040.93,348.49 2080.93,348.49 2120.93,348.49 2160.93,348.49 2200.93,348.49 2240.93,348.49 2280.93,348.49 1921.03,351.39 1666.56,356.86 2378.76,358.05 2457.7,361.02 1175.75,362.57 1883.52,365.27 6633.75,368.44 6334.56,369.63 6446.2,370.47 6486.2,370.47 6526.2,370.47 6603.25,370.47 6406.21,371.07 1109.01,372.25 6793.5,372.23 6673.51,372.82 6713.51,372.82 6753.51,372.82 7408.26,373.53 7448.25,372.93 7488.25,372.93 7528.25,372.93 7704.08,372.93 7744.08,372.93 7784.08,372.93 7824.07,373.53 1701.16,376.93 7334.96,383.66 1851.85,389.71 2359.48,393.1 6900.39,393.94 1191.87,399.18 2450.6,400.39 7901.41,401.2 1728.2,406.41 7401.41,406.47 6334.47,409.63 1118.94,411 1229.27,413.35 1269.27,413.35 1309.27,413.35 1349.27,413.35 1389.27,413.35 1429.27,413.35 1469.27,413.35 1509.27,413.35 1549.27,413.35 1589.27,413.35 2324.91,413.22 1964.99,415.78 2004.99,415.78 2044.99,415.78 2084.99,415.78 2124.99,415.78 2164.99,415.78 2204.99,415.78 2244.99,415.78 2284.99,415.78 6399.73,417.46 1628.84,419.21 1925.22,420.01 1828.91,422.48 6834.54,423.66 7335.56,423.66 7835.56,427.22 6899,433.92 2431.02,435.27 6695.74,438.69 6815.74,439.29 6754.53,440.26 6788.34,440.26 7900.81,441.19 1745.21,442.61 1141.29,444.18 1658.93,445.57 1893.7,444.64 7400.81,446.47 6595.18,447.49 6334.47,449.63 6399.73,457.46 1817.03,460.67 2401.39,462.14 7335.56,463.66 7835.56,467.22 1173.63,467.72 6882.94,470.55 6563.74,472.21 2364.46,477.52 1211.85,479.5 1251.83,480.65 1291.83,480.65 1331.83,480.65 1371.83,480.65 1411.83,480.65 1451.83,480.65 1491.83,480.65 1531.83,480.65 1571.83,480.65 2004.59,480.65 2044.59,480.65 2084.59,480.65 2124.59,480.65 2164.59,480.65 2204.59,480.65 2244.59,480.65 2284.59,480.65 2324.59,480.65 7900.81,481.19 1750.65,482.24 1882.65,483.09 1964.65,482.83 1668.65,484.37 7400.81,486.47 6334.47,489.63 6851.09,494.76 6399.73,497.46 1815.49,500.64 7336.34,503.65 6652.45,505.51 6732.45,505.51 6772.45,505.51 6812.45,505.1 1602.98,505.74 7833.45,507.17 6548.31,509.12 6613.66,515.28 7897.2,521.03 1745.3,521.88 1957.05,522.11 7410.34,525.32 6334.47,529.63 6410.35,536.02 1831.02,537.5 1621.35,541.27 7813.09,541.59 7346.09,542.45 6547.42,549.11 6612.67,555.26 7436.91,555.22 7882.43,558.2 1734.24,560.32 1945.24,560.32 6334.47,569.63 7784.8,569.88 4843.04,575 4921.78,575 5000.52,575 5079.26,575 5158,575 5236.74,575 5315.48,575 5394.58,575 6406.48,575.84 7366.96,576.57 1831.83,577.5 1621.58,581.27 7465.2,583.5 6547.42,589.11 7857.49,589.47 6612.67,595.26 7756.52,598.16 7394.75,605.34 6334.47,609.63 7493.48,611.79 6399.73,615.26 7829.2,617.76 7728.23,626.44 6549.24,629.06 6628.34,632.06 6668.34,632.26 6708.34,632.26 6748.34,632.26 6788.34,632.68 7423.03,633.62 7521.77,640.07 6827.47,640.99 7800.92,646.04 6334.47,649.63 6399.73,655.26 7699.98,654.76 6862.34,660.59 7451.32,661.91 1783,665 1995.91,665 6564.94,665.85 7548.74,669.61 7772.63,674.33 7676.9,687.43 6334.47,689.63 7479.6,690.19 6596.26,690.74 6887.87,691.38 6399.73,695.26 6635.68,697.51 6675.68,697.51 6715.68,697.51 6755.68,697.51 6795.64,699.35 7744.67,702.93 7566.75,705.32 7227.35,712.98 6829.37,720.85 7503.52,722.25 7664.7,725.53 6903.05,728.39 6334.47,729.63 6399.73,735.26 7728.82,739.66 7573.5,744.75 4715.74,750 4855.74,750 5100.74,750 5340.74,750 5485.74,750 6841.7,758.9 7508.2,761.98 7662.91,765.49 6906.98,768.2 6337.23,769.53 6407.7,774.46 7574.35,778.02 7726.32,779.58 6841.73,798.9 7515.38,801.33 6433.54,804.99 6350.93,807.11 6906.98,808.2 7533.26,837.11 6375.19,838.92 6841.73,838.9 6906.98,848.2 7691.84,850.74 6490.11,861.56 6841.73,878.9 6906.98,888.2 6518.4,889.84 6546.68,918.13 6843.09,918.88 4803.67,923.65 4882.77,923.65 4961.51,923.65 5040.25,923.65 5118.99,923.65 5197.73,923.65 5276.47,923.65 5355.21,923.65 6460.04,923.77 6913.31,927.7 6574.97,946.41 35,950 115,950 200,950 6488.33,952.06 6854.86,957.11 6938.37,958.88 6603.25,974.7 6516.61,980.34 6966.65,987.16 7837.35,987.98 6877.51,990.08 6631.53,1002.98 7001.88,1006.11 7081.86,1007.34 7121.86,1007.34 7161.86,1007.34 7201.86,1007.34 7241.86,1007.4 6544.89,1008.62 7281.23,1014.47 6905.68,1018.47 6659.82,1031.26 7317.11,1032.14 6573.18,1036.91 6934.84,1045.86 6688.1,1059.55 6601.46,1065.19 6970.08,1064.79 35,1070 115,1070 200,1070 7009.35,1072.36 7089.35,1072.59 7129.35,1072.59 7169.35,1072.59 7209.35,1072.59 7249.35,1072.31 7921.23,1073.14 6716.39,1087.83 6629.75,1093.48 7921.23,1098.14 6744.67,1116.12 6658.03,1121.76 6773.46,1143.88 6686.32,1150.05 6810.79,1158.25 6850.79,1158.64 6890.79,1158.64 6930.79,1158.64 6970.79,1158.64 7010.79,1158.64 7090.79,1158.64 7130.79,1158.64 7170.79,1158.64 7210.79,1158.64 7250.79,1158.77 6714.6,1178.33 7328.09,1190.17 6745.4,1203.85 7294.34,1211.64 6782.2,1219.54 7255.69,1221.97 6815.74,1223.89 6855.74,1223.89 6895.74,1223.89 6935.74,1223.89 7055.74,1223.89 7095.74,1223.89 7135.74,1223.89 7175.74,1223.89 7215.74,1223.89 7467.35,1232.98 7922.35,1292.98 35,1295 115,1295 200,1295 7467.35,1312.98 7922.35,1317.98 7467.35,1337.98 7922.35,1342.98 7467.35,1362.98 7922.35,1367.98 35,1415 115,1415 200,1415 35,1440.19 115,1440.19 200,1440.19 8162.61,1442.44 7792.35,1442.98 7817.35,1442.98 7842.35,1442.98 8162.61,1472.44 8162.61,1502.44 8162.61,1532.44 35,1560.19 115,1560.19 200,1560.19 7067.82,1690.62 7067.82,1720.62 7067.82,1750.62 7067.82,1780.62 35,1785.19 115,1785.19 200,1785.19 1360,1865 1385,1865 1410,1865 1435,1865 1460,1865 1485,1865 1510,1865 35,1905.19 115,1905.19 200,1905.19 375,2330 450,2330 375,2360 450,2360 375,2390 450,2390 2270,2540 2300,2540 2330,2540 2390,2580 2450,2580 115,2585 215,2585 310,2585 355,2585 1190,2600 115,2695 215,2695 310,2695 355,2695 995,2725 310,2750 355,2750 115,2975 215,2975 310,2975 355,2975 1130,3015 450,3055 115,3085 215,3085 310,3085 355,3085 1655,3205 1715,3205 1775,3205 1835,3205 1895,3205 1985,3205 9452.35,3614.14 9565.2,3614.43 9605.2,3614.43 9092.36,3615.09 9132.36,3614.67 9172.36,3614.67 9212.36,3614.67 9252.36,3614.67 9292.36,3614.67 9332.36,3614.67 9372.36,3614.67 9412.36,3614.67 9053.24,3623.43 9018.38,3643.06 8989.36,3670.59 9093.04,3680.59 9133.03,3679.92 9173.03,3679.92 9213.03,3679.92 9253.03,3679.92 9293.03,3679.92 9333.03,3679.92 9373.03,3679.92 9413.03,3679.92 9453.02,3680.59 9565.2,3680.3 9605.2,3680.3 9539.47,3692.25 2350,3695.79 2385,3695.79 2420,3695.79 2455,3695.79 2490,3695.79 2525,3695.79 2560,3695.79 9056.34,3696.51 8961.08,3698.87 2640,3714.21 2690,3714.21 2740,3714.21 9472.41,3714.91 9027.75,3724.48 8932.79,3727.15 2490,3730.79 2525,3730.79 2560,3730.79 9538.98,3732.25 8999.46,3752.77 8904.51,3755.44 9473.11,3754.9 9538.98,3772.25 2350,3789.21 2385,3789.21 2420,3789.21 2455,3789.21 9473.11,3794.9 9538.98,3812.25 2640,3814.21 2690,3814.21 2740,3814.21 9259.12,3827.61 9299.12,3827.61 9219.13,3828.66 9339.09,3829.12 9473.11,3834.9 8914.61,3837.62 8819.66,3840.29 9181.58,3842.43 9374.98,3846.78 585,3850.47 635,3850.47 685,3850.47 1770,3850.47 1820,3850.47 1870,3850.47 9544.49,3851.87 9154.75,3872.1 9543.17,3891.85 9232.03,3892.92 9272.03,3892.87 9312.03,3892.87 891,3895.39 917.91,3895.39 1755,3895.47 1885,3895.47 9145.97,3911.12 575,3915.47 695,3915.47 9403.22,3919.3 8829.76,3922.47 9337.97,3923.32 8734.8,3925.14 9211.22,3927.09 1755,3930.47 1885,3930.47 9545.8,3931.76 963,3935.39 575,3945.47 695,3945.47 8801.47,3950.76 9145.97,3951.12 8706.52,3953.43 9403.22,3959.3 963,3960 9337.97,3963.32 1755,3965.47 1885,3965.47 9211.22,3967.09 9538.98,3971.18 575,3975.47 695,3975.47 8773.19,3979.04 8678.24,3981.71 9145.97,3991.12 9473.11,3994.78 9403.22,3999.3 9337.97,4003.32 575,4005.47 695,4005.47 750,4005.47 780,4005.47 810,4005.47 840.47,4006.26 8744.9,4007.33 9211.22,4007.09 8650.49,4010.52 9538.98,4011.18 1560,4020.47 9145.97,4031.12 8716.62,4035.61 9473.11,4034.78 9403.22,4039.3 9337.97,4043.32 8629.82,4044.77 9211.22,4047.09 1560,4050.47 1590,4050.47 1620,4050.47 1650,4050.47 1680,4050.47 9538.98,4051.18 8691.44,4066.69 9144.99,4071.11 4120,4075 4175,4075 4230,4075 9473.1,4074.78 9403.22,4079.3 9337.97,4083.32 8620.31,4083.62 9208.47,4086.99 9539.66,4091.17 8684.84,4106.14 9126.36,4106.51 9564.23,4114.43 9604.23,4114.43 9421.78,4114.74 9473.79,4114.77 2350,4120.79 2385,4120.79 2420,4120.79 2455,4120.79 2490,4120.79 2525,4120.79 2560,4120.79 9089.25,4121.44 9049.25,4121.93 8619.59,4123.62 8929.27,4122.88 9344.79,4122.73 9194.78,4124.58 8890.64,4133.29 2640,4139.21 2690,4139.21 2740,4139.21 8684.84,4146.14 8856.88,4154.74 9169.51,4155.58 2490,4155.79 2525,4155.79 2560,4155.79 9366.01,4156.64 8619.59,4163.62 4120,4175 4175,4175 4230,4175 9135.44,4176.53 9400.19,4177.41 9440.07,4180.59 9566.22,4180.3 9606.22,4180.3 9472,4181 8828.23,4182.65 8684.84,4186.14 9096.66,4186.37 9056.67,4187.18 8936.68,4187.85 8619.59,4203.62 8899.99,4203.79 8800.59,4211.56 2350,4214.21 2385,4214.21 2420,4214.21 2455,4214.21 8684.84,4226.14 8871.4,4231.77 2640,4239.21 2690,4239.21 2740,4239.21 8619.59,4243.62 8780.42,4246.11 8845.1,4261.9 8684.84,4266.14 8619.59,4283.62 8771.47,4285.09 8836.14,4300.89 8684.84,4306.14 8619.59,4323.62 8770.89,4325.09 8836.14,4340.89 8684.84,4346.14 8619.59,4363.62 8770.89,4365.09 8836.14,4380.89 8684.84,4386.14 8619.59,4403.62 8770.89,4405.09 550,4420.47 8836.14,4420.89 8684.84,4426.14 1100,4430 1150,4430 1200,4430 8619.59,4443.62 1030,4445 1240,4445 8770.89,4445.09 550,4460.47 8836.14,4460.89 8684.84,4466.14 1030,4475 1240,4475 8619.59,4483.62 8068.82,4484.38 8770.89,4485.09 8836.14,4500.89 1030,4505 1240,4505 8684.84,4506.14 9130.5,4507.55 8068.82,4514.38 8620.28,4523.61 8771.3,4525.09 8833.81,4540.82 8068.82,4544.38 8627.29,4562.99 8068.82,4574.38 8822.02,4579.05 8645.46,4598.63 2350,4605.79 2385,4605.79 2420,4605.79 2455,4605.79 2490,4605.79 2525,4605.79 2560,4605.79 9568.46,4614.45 9608.46,4614.45 9455.9,4615.16 9415.9,4615.76 2640,4624.21 2690,4624.21 2740,4624.21 9297.44,4627.77 2490,4640.79 2525,4640.79 2560,4640.79 9263.96,4649.67 9235.41,4677.68 9562.41,4680.32 9602.41,4680.32 9402.98,4681.01 9442.98,4681.61 9323.54,4687.67 9536.9,4695.68 2350,4699.21 2385,4699.21 2420,4699.21 2455,4699.21 9207.12,4705.96 9292.49,4712.88 2640,4724.21 2690,4724.21 2740,4724.21 9178.84,4734.25 9536.41,4735.68 9264.2,4741.17 8505.5,4747.55 8610.5,4747.55 9150.56,4762.53 9235.92,4769.45 9536.41,4775.68 9117.39,4784.88 9077.54,4788.4 9038.42,4796.76 9207.63,4797.74 585,4800.47 635,4800.47 685,4800.47 1100,4800.47 1150,4800.47 1200,4800.47 1770,4810 1820,4810 1870,4810 9003.23,4815.77 9536.41,4815.68 9178.61,4825.27 891,4845.39 917.91,4845.39 8286,4845 9143.76,4844.89 9104.64,4853.23 9064.68,4854.97 9540.01,4855.52 575,4865.47 695,4865.47 1755,4880.47 1885,4880.47 963,4885.39 575,4895.47 695,4895.47 963,4910 1755,4915.47 1885,4915.47 575,4925.47 695,4925.47 9540.8,4935.13 9082.06,4943.13 9121.98,4945.64 575,4955.47 695,4955.47 750,4955.47 780,4955.47 810,4955.47 840.47,4956.26 9159.68,4959.01 1560,4970.47 9536.41,4974.89 9191.64,4983.06 1560,5000.47 1590,5000.47 1620,5000.47 1650,5000.47 1680,5000.47 9103.71,5009.03 9219.93,5011.34 9536.41,5014.89 9140.46,5024.82 2350,5030.79 2385,5030.79 2420,5030.79 2455,5030.79 2490,5030.79 2525,5030.79 2560,5030.79 9248.21,5039.63 2640,5049.21 2690,5049.21 2740,5049.21 9169.08,5052.77 9536.41,5054.89 2490,5065.79 2525,5065.79 2560,5065.79 9276.49,5067.91 8400.5,5072.55 9197.36,5081.06 9537.01,5094.89 9304.77,5096.21 8400.5,5097.55 9225.64,5109.34 9571.04,5113.36 9611.04,5113.36 9340.27,5114.64 9380.25,5115.78 9420.25,5115.78 8855.5,5117.55 8400.5,5122.55 2350,5124.21 2385,5124.21 2420,5124.21 2455,5124.21 9253.93,5137.63 2640,5149.21 2690,5149.21 2740,5149.21 9322.34,5177.39 9362.18,5181.03 9402.18,5181.03 9563.05,5180.65 9603.05,5180.65 8745.34,5201.43 8770.34,5201.43 8475.5,5202.55 8500.5,5202.55 8525.5,5202.55 8550.5,5202.55 550,5370.47 1030,5395 1240,5395 550,5410.47 1030,5425 1240,5425 8313.44,5442.61 8343.44,5442.61 8373.44,5442.61 8403.44,5442.61 1030,5455 1240,5455 6634.68,5538.22 2350,5551.57 2385,5551.57 2420,5551.57 2455,5551.57 2490,5551.57 2525,5551.57 2560,5551.57 2640,5570 2690,5570 2740,5570 2350,5645 2385,5645 2420,5645 2455,5645 2640,5670 2690,5670 2740,5670 585,5705 635,5705 685,5705 1100,5705 1150,5705 1200,5705 1870,5715 891,5749.92 917.91,5749.92 1755,5750 1885,5750 575,5770 695,5770 1755,5785 1885,5785 963,5789.92 575,5800 695,5800 963,5814.53 1755,5820 1885,5820 575,5830 695,5830 575,5860 695,5860 750,5860 780,5860 810,5860 840.47,5860.79 1560,5875 1560,5905 1590,5905 1620,5905 1650,5905 1680,5905 2350,5976.57 2385,5976.57 2420,5976.57 2455,5976.57 2490,5976.57 2525,5976.57 2560,5976.57 2640,5995 2690,5995 2740,5995 2490,6011.57 2525,6011.57 2560,6011.57 2350,6070 2385,6070 2420,6070 2455,6070 2640,6095 2690,6095 2740,6095 7543.94,6241.75 7823.94,6241.75 8930,6245 7543.94,6271.75 7823.94,6271.75 550,6275 8930,6275 9210,6275 1030,6300 1240,6300 7543.94,6301.75 7823.94,6301.75 8930,6305 550,6315 1030,6330 1240,6330 7543.94,6331.75 7823.94,6331.75 8930,6335 9210,6335 1030,6360 1240,6360 7543.94,6361.75 7823.94,6361.75 8930,6365 9210,6365 7543.94,6391.75 7823.94,6391.75 8930,6395 7543.94,6421.75 9210,6425 7543.94,6451.75 9210,6455 7543.94,6606.75 9210,6610 7543.94,6636.75 9210,6640 7543.94,6666.75 7823.94,6666.75 8930,6670 885,6695 7543.94,6696.75 7823.94,6696.75 8930,6700 9210,6700 7543.94,6726.75 7823.94,6726.75 885,6730 920,6730 955,6730 8930,6730 9210,6730 7543.94,6756.75 7823.94,6756.75 8930,6760 885,6765 7543.94,6786.75 7823.94,6786.75 8930,6790 9210,6790 7823.94,6816.75 8930,6820 9210,6820 2520,6955 2365,6970 2415,6970 2465,6970 2110,6975 2155,6975 2200,6975 2245,6985 2520,7005 2520,7055 1875,7065 1910,7065 1945,7065 560,7070 680,7070 2065,7075 2110,7100 2155,7100 2200,7100 1570,7105 560,7110 680,7110 2365,7115 2415,7115 2465,7115 745,7140 795,7140 845,7140 895,7140 945,7140 1570,7145 560,7150 680,7150 1230,7150 1280,7150 1330,7150 1055,7160 1105,7160 1155,7160 745,7170 1570,7185 1020,7190 745,7200 1645,7200 1680,7200 1715,7200 1020,7220 745,7230 1230,7245 1280,7245 1330,7245 1055,7255 1105,7255 1155,7255 745,7260 2105,7270 745,7290 1450,7295 2105,7305 2105,7340 1640,7640 1670,7640 1700,7640 1730,7640 1460,7655 1460,7685 1460,7715 1565,7715 1595,7715 1625,7715 1655,7715 2070,7725 2100,7725 1805,7740 1925,7740 1460,7745 1565,7745 1805,7770 1925,7770 1565,7775 1805,7800 1925,7800 1535,7805 1565,7805 1200,7820 1315,7820 1360,7820 1410,7820 1460,7820 1805,7830 1535,7835 1565,7835 1200,7870 1315,7870 1200,7920 1315,7920 1360,7920 1410,7920 1460,7920 1040,7995 1090,7995 1140,7995 1745,8005 870,8025 1745,8035 870,8055 7185,8055 1745,8065 870,8085 7185,8085 1040,8095 1090,8095 1140,8095 1745,8095 7185,8115 1745,8125 7185,8145 929,8170 929,8200 929,8230 929,8260 2180,8280 2210,8280 2240,8280 6675,8295 6070,8310 6070,8340 6070,8370 644.91,8378 6070,8400 6390,8400 6415,8400 6440,8400 644.91,8408 644.91,8438 6310,8475 6765,8480 6310,8500 6765,8505 6310,8525 6765,8530 6310,8550 6765,8610 7028.66,8619.09 7068.66,8619.09 7108.66,8619.09 7148.66,8619.09 7188.66,8619.09 7228.66,8619.09 7268.66,8619.09 7308.66,8619.09 7348.66,8619.09 7388.66,8619.09 6988.67,8619.84 7428.66,8619.8 6949.29,8626.84 7467.53,8629.22 6913.72,8645.15 7501.82,8649.81 1275,8670 1310,8670 1345,8670 1380,8670 1415,8670 1450,8670 2690,8670 2725,8670 2760,8670 2795,8670 2830,8670 2865,8670 7530.65,8677.55 7011.79,8684.35 7051.79,8684.35 7091.79,8684.35 7131.79,8684.35 7171.79,8684.35 7211.79,8684.35 7251.79,8684.35 7291.79,8684.35 7331.79,8684.35 7371.79,8684.35 7411.79,8684.35 590,8690 635,8690 680,8690 2005,8690 2050,8690 2095,8690 7450.72,8693.54 7558.93,8705.83 1180,8710 1215,8710 1250,8710 2595,8710 2630,8710 2665,8710 7480.76,8719.95 7587.21,8734.12 6311.12,8744.84 7509.05,8748.23 7615.5,8762.4 6311.12,8769.84 6980.19,8770.39 7020.19,8770.39 7060.19,8770.39 7100.19,8770.39 7140.19,8770.39 7180.19,8770.39 7220.19,8770.4 585,8775 690,8775 2000,8775 2105,8775 7537.33,8776.52 7259.61,8777.22 7643.78,8790.69 1310,8795 1345,8795 1380,8795 1415,8795 2725,8795 2760,8795 2795,8795 2830,8795 7295.17,8795.54 7565.62,8804.8 7672.07,8818.97 585,8820 690,8820 2000,8820 2105,8820 6931.15,8820.21 7324.69,8822.53 6969.1,8832.84 7593.9,8833.09 7009.01,8835.65 7049.01,8835.65 7089.01,8835.65 7129.01,8835.65 7169.01,8835.65 7209.01,8835.65 7248.26,8843.33 7700.35,8847.25 7353.01,8850.77 6395,8855 7622.18,8861.37 585,8865 690,8865 2000,8865 2105,8865 7278.91,8869.03 7728.64,8875.54 1180,8880 1215,8880 1250,8880 2595,8880 2630,8880 2665,8880 7376.15,8883.4 7650.47,8889.65 7307.07,8897.44 7756.92,8903.82 7678.75,8917.94 1275,8920 1310,8920 1345,8920 1380,8920 1415,8920 1450,8920 2690,8920 2725,8920 2760,8920 2795,8920 2830,8920 2865,8920 7388.8,8921.35 7785.2,8932.11 7324.43,8933.48 7707.04,8946.22 7813.49,8960.39 7390.62,8961.31 7325.37,8973.47 6664.6,8974.09 7735.32,8974.51 7841.77,8988.68 6694.96,9000.13 7390.62,9001.31 7763.61,9002.79 7325.37,9013.47 7869.32,9017.68 6518.09,9023.81 7791.89,9031.08 6714.84,9034.84 7390.62,9041.31 7889.01,9052.49 7325.37,9053.47 7819.48,9060.04 6506.15,9061.98 6569.74,9073.6 6724.45,9073.67 7390.62,9081.31 7897.43,9091.6 7325.96,9093.46 7832.48,9097.87 6503.36,9101.89 6659.22,9106.82 6568.58,9113.58 6726.98,9113.59 7401.39,9119.83 7005,9130 7897.88,9131.6 7334.98,9132.43 7832.63,9137.87 6488.22,9138.91 7434.11,9142.84 7474.02,9145.47 7514.02,9145.47 7554.02,9145.47 7594.02,9145.47 6668.36,9145.76 6748.01,9147.62 7633.63,9151.07 6557.39,9151.99 6460.35,9167.6 7355.2,9166.94 7897.88,9171.6 7665.67,9175.01 6776.29,9175.9 7832.63,9177.87 6615,9180 6688.67,9180.22 6535.29,9185.33 7385.66,9192.87 6432.06,9195.88 6804.58,9204.19 7422.95,9207.35 6716.34,9209.1 1670,9210 1700,9210 1730,9210 3080,9210 3110,9210 3140,9210 4820.89,9211.35 4899.63,9211.35 4978.37,9211.35 5057.11,9211.35 5135.85,9211.35 5214.59,9211.35 5293.33,9211.35 7462.81,9210.72 7502.81,9210.72 7542.81,9210.72 7582.81,9210.72 7682.72,9211.2 7897.88,9211.6 6507.24,9213.85 7832.63,9217.87 6403.78,9224.16 7619.1,9227.54 6832.86,9232.47 6744.63,9237.39 6478.96,9242.13 7684.94,9251.13 7897.88,9251.6 6375.49,9252.45 7832.63,9257.87 6861.05,9260.85 6772.91,9265.67 7619.68,9267.54 6450.67,9270.42 705,9290 735,9290 795,9290 825,9290 885,9290 915,9290 2120,9290 2150,9290 2210,9290 2240,9290 2300,9290 2330,9290 7684.94,9291.13 7897.88,9291.6 6801.2,9293.95 6883.79,9293.76 7832.63,9297.87 6422.39,9298.7 7619.68,9307.54 5380,9310 705,9320 735,9320 795,9320 825,9320 885,9320 915,9320 2120,9320 2150,9320 2210,9320 2240,9320 2300,9320 2330,9320 6335.17,9320.56 6825.83,9325.47 7684.41,9331.13 7897.88,9331.6 6400.35,9332.08 6895.6,9331.98 7433.15,9337.47 7473.15,9337.47 7513.15,9337.47 7553.15,9337.47 7593.15,9337.47 7832.63,9337.87 7393.55,9343.16 6331.23,9360.36 7358.86,9363.08 6831.23,9365.1 7670.31,9368.56 7897.88,9371.6 6397.1,9371.95 6897.1,9371.95 7832.63,9377.87 4690,9385 4835,9385 5320,9385 5460,9385 7639.6,9394.19 7336.11,9395.98 6331.23,9400.36 7440.52,9402.72 7480.52,9402.72 7520.52,9402.72 7560.52,9402.72 7600.52,9402.72 6831.23,9405.1 7897.88,9411.6 6397.1,9411.95 6897.1,9411.95 7401.71,9412.42 7832.63,9417.87 7332.55,9435.82 6330.59,9440.36 6830.64,9445.1 7898.13,9451.6 6397.64,9451.94 6897.69,9451.94 7405.17,9472.1 7445.17,9472.7 7485.17,9472.7 7525.17,9472.7 7752.78,9472.7 7792.78,9472.7 7832.78,9472.81 6330.89,9499.65 7331.96,9500.13 6897.39,9503.8 7898.13,9503.7 6831.54,9536.59 7832.56,9537.15 7442.74,9538.56 7482.74,9538.56 7522.74,9538.56 7703.66,9538.56 7743.66,9538.56 7783.66,9538.56 7402.74,9538.96 6331.54,9539.65 7332.56,9540.13 7663.8,9541.88 6396.79,9543.8 6896.79,9543.79 7897.81,9543.7 4781.16,9560 4860.26,9560 4939,9560 5017.74,9560 5096.48,9560 5175.22,9560 5253.96,9560 5332.7,9560 6831.54,9576.59 7332.56,9580.13 6896.79,9583.79 7397.81,9583.7
  other v2: 1685,2247.6 1657.44,2285 1712.56,2285 1685,2322.4 2539.45,2404.72 2584.72,2404.72 2630,2404.72 2675.28,2404.72 2720.55,2404.72 2539.45,2450 2584.72,2450 2630,2450 2675.28,2450 2720.55,2450 2539.45,2495.28 2584.72,2495.28 2630,2495.28 2675.28,2495.28 2720.55,2495.28 2590,3125.16 2562.44,3162.56 2617.56,3162.56 2590,3199.96 2590,3457.6 2562.44,3495 2617.56,3495 2590,3532.4 1041.73,4043.43 1085.04,4043.43 1128.35,4043.43 1171.65,4043.43 1214.96,4043.43 1258.27,4043.43 1041.73,4086.73 1085.04,4086.73 1128.35,4086.73 1171.65,4086.73 1214.96,4086.73 1258.27,4086.73 1041.73,4130.04 1085.04,4130.04 1128.35,4130.04 1171.65,4130.04 1214.96,4130.04 1258.27,4130.04 1041.73,4173.35 1085.04,4173.35 1128.35,4173.35 1171.65,4173.35 1214.96,4173.35 1258.27,4173.35 1041.73,4216.65 1085.04,4216.65 1128.35,4216.65 1171.65,4216.65 1214.96,4216.65 1258.27,4216.65 1041.73,4259.96 1085.04,4259.96 1128.35,4259.96 1171.65,4259.96 1214.96,4259.96 1258.27,4259.96 1041.73,4303.27 1085.04,4303.27 1128.35,4303.27 1171.65,4303.27 1214.96,4303.27 1258.27,4303.27 1041.73,4346.57 1085.04,4346.57 1128.35,4346.57 1171.65,4346.57 1214.96,4346.57 1258.27,4346.57 1041.73,4993.43 1085.04,4993.43 1128.35,4993.43 1171.65,4993.43 1214.96,4993.43 1258.27,4993.43 1041.73,5036.73 1085.04,5036.73 1128.35,5036.73 1171.65,5036.73 1214.96,5036.73 1258.27,5036.73 1041.73,5080.04 1085.04,5080.04 1128.35,5080.04 1171.65,5080.04 1214.96,5080.04 1258.27,5080.04 1041.73,5123.35 1085.04,5123.35 1128.35,5123.35 1171.65,5123.35 1214.96,5123.35 1258.27,5123.35 1041.73,5166.65 1085.04,5166.65 1128.35,5166.65 1171.65,5166.65 1214.96,5166.65 1258.27,5166.65 1041.73,5209.96 1085.04,5209.96 1128.35,5209.96 1171.65,5209.96 1214.96,5209.96 1258.27,5209.96 1041.73,5253.27 1085.04,5253.27 1128.35,5253.27 1171.65,5253.27 1214.96,5253.27 1258.27,5253.27 1041.73,5296.57 1085.04,5296.57 1128.35,5296.57 1171.65,5296.57 1214.96,5296.57 1258.27,5296.57 1041.73,5897.95 1085.04,5897.95 1128.35,5897.95 1171.65,5897.95 1214.96,5897.95 1258.27,5897.95 1041.73,5941.26 1085.04,5941.26 1128.35,5941.26 1171.65,5941.26 1214.96,5941.26 1258.27,5941.26 1041.73,5984.57 1085.04,5984.57 1128.35,5984.57 1171.65,5984.57 1214.96,5984.57 1258.27,5984.57 1041.73,6027.87 1085.04,6027.87 1128.35,6027.87 1171.65,6027.87 1214.96,6027.87 1258.27,6027.87 1041.73,6071.18 1085.04,6071.18 1128.35,6071.18 1171.65,6071.18 1214.96,6071.18 1258.27,6071.18 1041.73,6114.49 1085.04,6114.49 1128.35,6114.49 1171.65,6114.49 1214.96,6114.49 1258.27,6114.49 1041.73,6157.8 1085.04,6157.8 1128.35,6157.8 1171.65,6157.8 1214.96,6157.8 1258.27,6157.8 1041.73,6201.1 1085.04,6201.1 1128.35,6201.1 1171.65,6201.1 1214.96,6201.1 1258.27,6201.1 7690,6480.79 9063.94,6482.54 7650.63,6530 7690,6530 7729.37,6530 9024.57,6531.75 9063.94,6531.75 9103.31,6531.75 7690,6579.21 9063.94,6580.96 1634.72,6847.01 1680,6847.01 1725.28,6847.01 1634.72,6892.28 1680,6892.28 1725.28,6892.28 1634.72,6937.56 1680,6937.56 1725.28,6937.56 1634.72,6982.83 1680,6982.83 1725.28,6982.83 1634.72,7028.11 1680,7028.11 1725.28,7028.11 1250.89,7403.37 1309.11,7403.37 1250.89,7450.02 1309.11,7450.02 1250.89,7496.67 1309.11,7496.67 1250.89,7543.33 1309.11,7543.33 1250.89,7589.98 1309.11,7589.98 1250.89,7636.63 1309.11,7636.63 780.98,8686.73 824.29,8686.73 867.6,8686.73 910.91,8686.73 954.21,8686.73 997.52,8686.73 1040.83,8686.73 1084.13,8686.73 2195.98,8686.73 2239.29,8686.73 2282.6,8686.73 2325.91,8686.73 2369.21,8686.73 2412.52,8686.73 2455.83,8686.73 2499.13,8686.73 780.98,8730.04 824.29,8730.04 867.6,8730.04 910.91,8730.04 954.21,8730.04 997.52,8730.04 1040.83,8730.04 1084.13,8730.04 2195.98,8730.04 2239.29,8730.04 2282.6,8730.04 2325.91,8730.04 2369.21,8730.04 2412.52,8730.04 2455.83,8730.04 2499.13,8730.04 780.98,8773.35 824.29,8773.35 867.6,8773.35 910.91,8773.35 954.21,8773.35 997.52,8773.35 1040.83,8773.35 1084.13,8773.35 2195.98,8773.35 2239.29,8773.35 2282.6,8773.35 2325.91,8773.35 2369.21,8773.35 2412.52,8773.35 2455.83,8773.35 2499.13,8773.35 780.98,8816.65 824.29,8816.65 867.6,8816.65 910.91,8816.65 954.21,8816.65 997.52,8816.65 1040.83,8816.65 1084.13,8816.65 2195.98,8816.65 2239.29,8816.65 2282.6,8816.65 2325.91,8816.65 2369.21,8816.65 2412.52,8816.65 2455.83,8816.65 2499.13,8816.65 780.98,8859.96 824.29,8859.96 867.6,8859.96 910.91,8859.96 954.21,8859.96 997.52,8859.96 1040.83,8859.96 1084.13,8859.96 2195.98,8859.96 2239.29,8859.96 2282.6,8859.96 2325.91,8859.96 2369.21,8859.96 2412.52,8859.96 2455.83,8859.96 2499.13,8859.96 780.98,8903.27 824.29,8903.27 867.6,8903.27 910.91,8903.27 954.21,8903.27 997.52,8903.27 1040.83,8903.27 1084.13,8903.27 2239.29,8903.27 2282.6,8903.27 2325.91,8903.27 2369.21,8903.27 2412.52,8903.27 2455.83,8903.27 2499.13,8903.27 1675.91,9145 1719.21,9145 3085.91,9145 3129.21,9145
  other v3: 5011.26,4846.26 5050.63,4846.26 5090,4846.26 5129.37,4846.26 5168.74,4846.26 5011.26,4885.63 5050.63,4885.63 5090,4885.63 5129.37,4885.63 5168.74,4885.63 5011.26,4925 5050.63,4925 5168.74,4925 5011.26,4964.37 5050.63,4964.37 5090,4964.37 5129.37,4964.37 5168.74,4964.37 5011.26,5003.74 5050.63,5003.74 5090,5003.74 5129.37,5003.74 5168.74,5003.74
  other v4: 6625.69,5375.08 6631.34,5406.19 6616.49,5435.18 6556.39,5444.37 6587.5,5450.03 6540.83,5459.93 6617.91,5480.43 6546.49,5491.04 6531.64,5520.03 6576.9,5521.45 6471.54,5529.23 6502.65,5534.88 6752.97,5587.21 6740.24,5599.94 6764.28,5623.98 6795.39,5629.63 6735.29,5638.83 6696.4,5643.78 6683.67,5656.5 6720.44,5667.82 6726.1,5698.93
  other v5: 6654.68,5367.3 6658.21,5448.61 6764.28,5554.68 6463.76,5558.22 6845.6,5558.22 6545.08,5561.75 6651.14,5667.82 6654.68,5749.14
